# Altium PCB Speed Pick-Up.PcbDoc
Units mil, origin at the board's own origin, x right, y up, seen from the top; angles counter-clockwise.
Board outline 393.7 x 393.7 mil, 2 copper layers (Top Layer, Bottom Layer), stack 61.855 mil thick; 6 components, 4 nets, 13 pads, 4 vias.
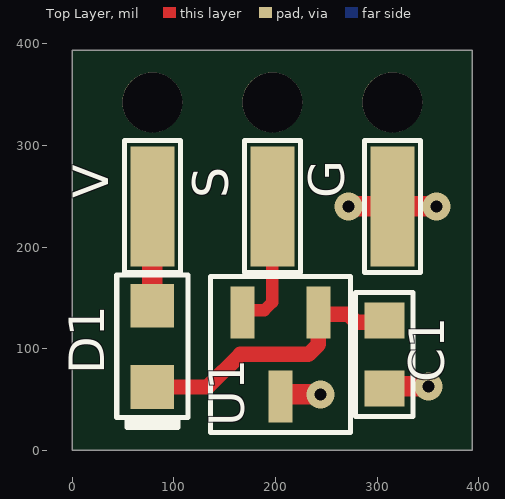
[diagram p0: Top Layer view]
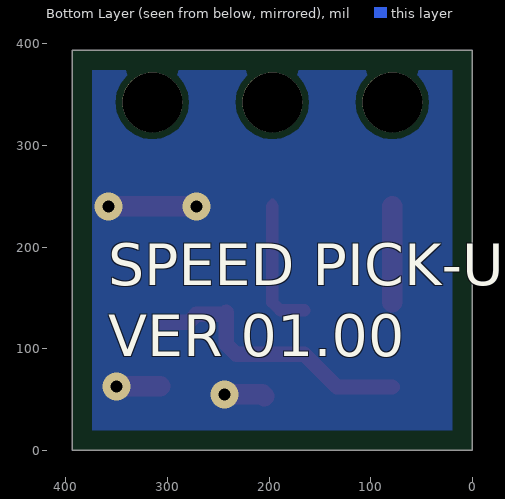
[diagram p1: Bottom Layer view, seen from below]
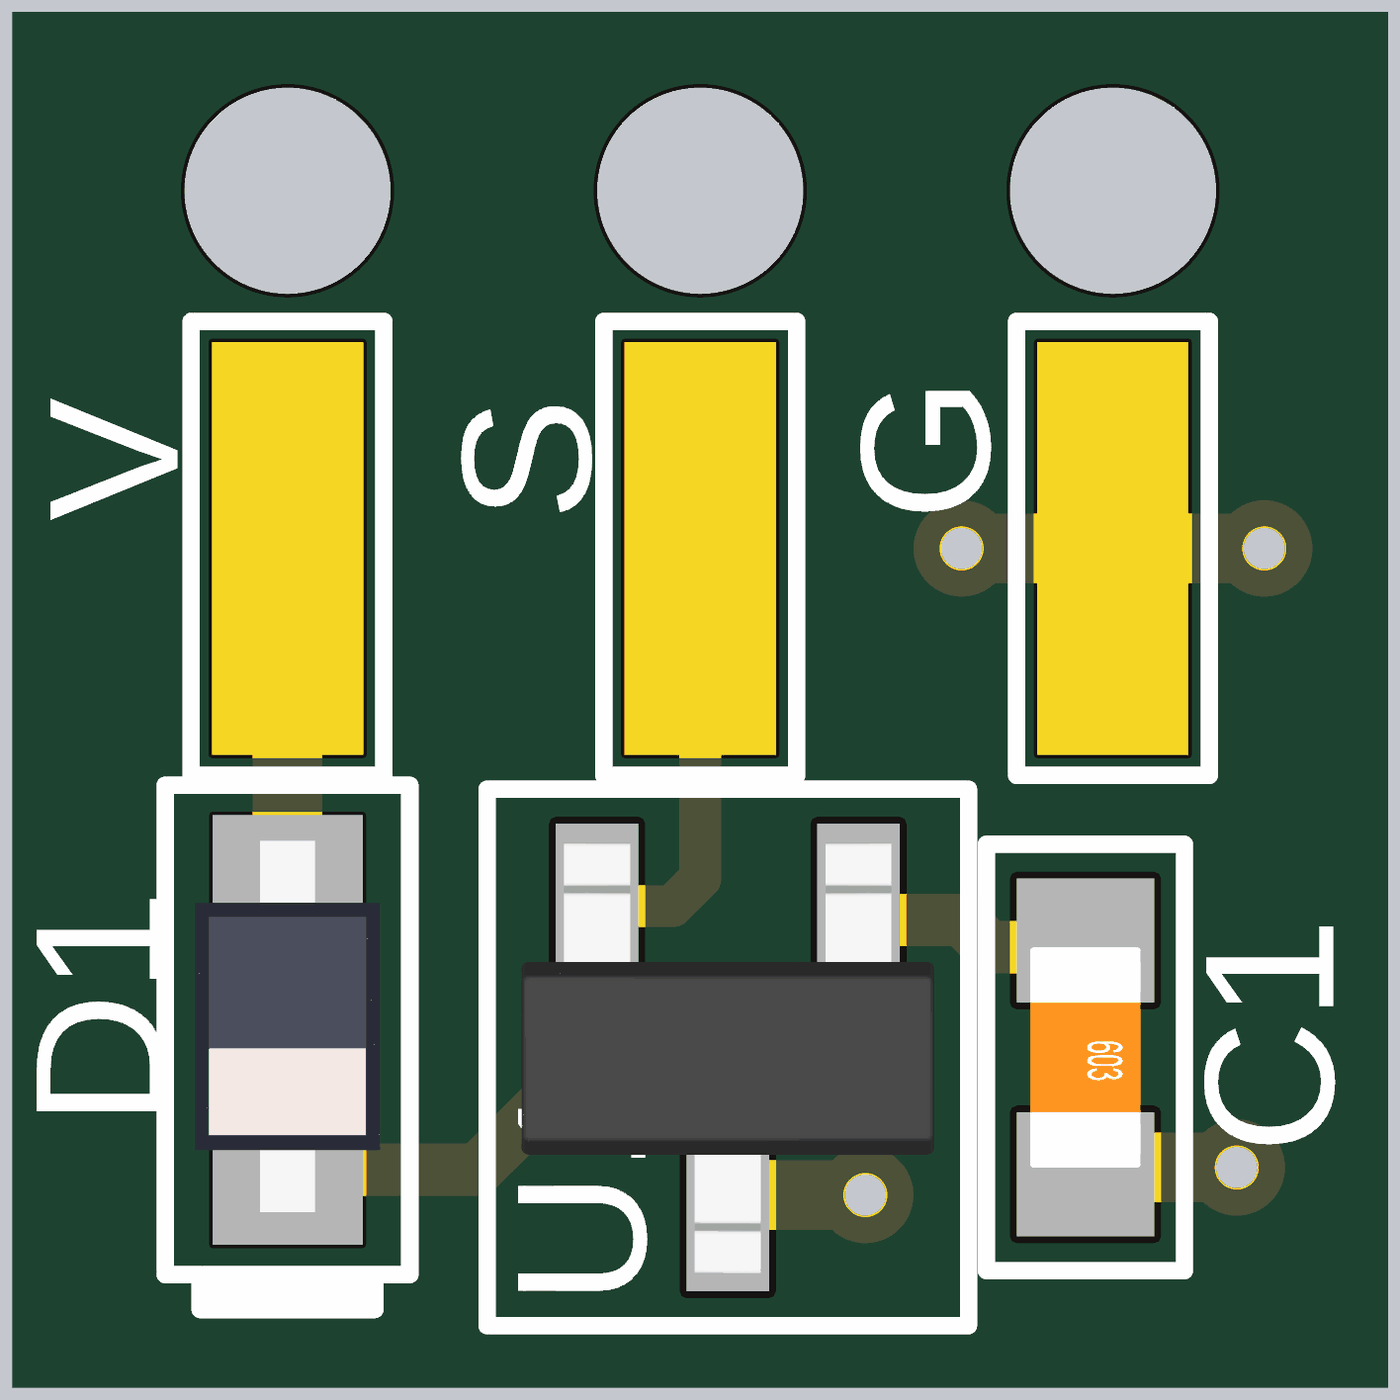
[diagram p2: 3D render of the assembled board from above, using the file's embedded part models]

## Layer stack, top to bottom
Top Solder: solder mask 0.4, Solder Resist, Dk 3.5
Top Layer: signal copper 1.4
Dielectric1: prepreg 59.0551, FR-4, Dk 4.2
Bottom Layer: signal copper 1.4
Bottom Solder: solder mask 0.4, Solder Resist, Dk 3.5

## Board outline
0,0 0,393.7 393.7,393.7 393.7,0

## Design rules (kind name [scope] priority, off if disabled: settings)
Clearance [All] p1: gap=6.69
ComponentClearance [All] p1: gap=0 collisioncheckmode=3 verticalgap=1 showdistances=FALSE
FabricationTestPointUsage TestPointUsage [All] p1: valid=0 allowmultiple=FALSE
FabricationTestpoint Testpoint [All] p1: side=3 testpointundercomponent=TRUE minsize=40 maxsize=100 preferedsize=60 minholesize=0 maxholesize=40 preferedholesize=32 testpointgrid=1 allowsidetop=TRUE allowsidebottom=TRUE usegrid=TRUE gridtolerance=0.01
HoleSize [All] p1: absolutevalues=TRUE maxlimit=196.85 minlimit=9.84 maxpercent=80.000 minpercent=20.000
PlaneClearance [All] p1: clearance=19.68
PolygonConnect PolygonConnect_8 [All vs IsNamedPolygon('Top - GND1-HSK')] p1: connectstyle=Direct reliefconductorwidth=10 reliefentries=4 polygonreliefangle="90 Angle" airgapwidth=10
PolygonConnect PolygonConnect_7 [All vs IsNamedPolygon('Bot - GND1-HSK')] p2: connectstyle=Direct reliefconductorwidth=10 reliefentries=4 polygonreliefangle="90 Angle" airgapwidth=10
PolygonConnect PolygonConnect_6 [All vs IsNamedPolygon('Bot - GND4a') Or  IsNamedPolygon('Bot - GND2a') Or  IsNamedPolygon('Bot - GND3a')] p3: connectstyle=Direct reliefconductorwidth=10 reliefentries=4 polygonreliefangle="90 Angle" airgapwidth=10
PolygonConnect PolygonConnect_5 [All vs IsNamedPolygon('Bot - GND1a')] p4: connectstyle=Direct reliefconductorwidth=10 reliefentries=4 polygonreliefangle="90 Angle" airgapwidth=10
PolygonConnect PolygonConnectVia [All vs isvia] p5: connectstyle=Direct reliefconductorwidth=9.84 reliefentries=4 polygonreliefangle="90 Angle" airgapwidth=10
PolygonConnect PolygonConnect_4 [All vs IsNamedPolygon('Bot - GND2')] p6: connectstyle=Relief reliefconductorwidth=30 reliefentries=4 polygonreliefangle="90 Angle" airgapwidth=10
PolygonConnect PolygonConnect_3 [All vs IsNamedPolygon('Bot - GND1')] p7: connectstyle=Relief reliefconductorwidth=30 reliefentries=4 polygonreliefangle="90 Angle" airgapwidth=10
PolygonConnect PolygonConnect_2 [All vs IsNamedPolygon('Bot - GND4')] p8: connectstyle=Relief reliefconductorwidth=30 reliefentries=4 polygonreliefangle="90 Angle" airgapwidth=10
PolygonConnect PolygonConnect_1 [All vs IsNamedPolygon('Bot - GND3')] p9: connectstyle=Relief reliefconductorwidth=30 reliefentries=4 polygonreliefangle="90 Angle" airgapwidth=10
PolygonConnect [All] p10: connectstyle=Relief reliefconductorwidth=15.75 reliefentries=4 polygonreliefangle="90 Angle" airgapwidth=10
RoutingCorners [All] p1: cornerstyle=45-Degree minsetback=98.43 maxsetback=98.43
RoutingVias [All] p1: holewidth=11.81 width=27.56 viastyle="Through Hole" minholewidth=11.81 minwidth=27.56 maxholewidth=11.81 maxwidth=27.56
ShortCircuit ShortCircuit_LK1 [(InComponent('LK1'))] p1: allowed=TRUE
ShortCircuit ShortCircuit_LK2 [(InComponent('LK2'))] p2: allowed=TRUE
ShortCircuit ShortCircuit_LK3 [(InComponent('LK3'))] p3: allowed=TRUE
ShortCircuit [All] p4: allowed=FALSE
SilkToSolderMaskClearance SilkscreenOverComponentPads [IsPad] p1: minsilkscreentomaskgap=10 clearancetoexposedcopper=TRUE
SolderMaskExpansion [All] p1: expansion=1.97
Width "Width_High Power" [InNetClass('High Power')] p1: maxlimit=59.06 minlimit=19.68 preferedwidth=39.37
Width Width_Power [InNetClass('Power')] p2: maxlimit=39.37 minlimit=11.81 preferedwidth=19.68
Width [All] p3: maxlimit=78.74 minlimit=7.87 preferedwidth=7.87
22 further rules are at their usual default settings.

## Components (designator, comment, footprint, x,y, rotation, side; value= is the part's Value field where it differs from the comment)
C1 "10nF_C0603_50V_10%_X7R" CAPC0603X85N 307.09,94.49 r270 top
D1 "1N4148WS" SOD323 78.74,102.36 r90 top
G "Pad-SMD-1.1x3.0mm-H_Rectangle" "PAD-SMD-1.1x3.0mm Rect" 314.96,240.16 r0 top
S "Pad-SMD-1.1x3.0mm-H_Rectangle" "PAD-SMD-1.1x3.0mm Rect" 196.85,240.16 r0 top
U1 "TLE4946-2K" SOT23 204.72,94.49 r270 top
V "Pad-SMD-1.1x3.0mm-H_Rectangle" "PAD-SMD-1.1x3.0mm Rect" 78.74,240.16 r0 top

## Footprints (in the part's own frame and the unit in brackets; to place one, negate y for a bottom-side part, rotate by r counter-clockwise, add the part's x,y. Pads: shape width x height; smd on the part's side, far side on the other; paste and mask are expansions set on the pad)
CAPC0603X85N [mm] "Chip Capacitor, 0603, 2-Leads, Body 1.6x0.8mm, IPC Medium Density"
  rect 0.9x1 smd paste+0 mask+0.05: 1(-0.85,0) 2(0.85,0)
  silkscreen extent -1.55,-0.72 1.55,0.72, body extent -0.8,-0.4 0.8,0.4, height 0.85
"PAD-SMD-1.1x3.0mm Rect" [mm] "Pad SMD, 1.1x3.0mm Rect"
  rect 1.1x3 smd paste-2.5 mask+0.025: 1(0,0)
  silkscreen extent -0.7,-1.65 0.7,1.65, body extent -0.55,-1.5 0.55,1.5, height 0.01
SOD323 [mil] "Diode, SOD323 2-Leads, Body 1.7x1.25mm, IPC Medium Density"
  rect 43x43 smd mask+0.98: 1(-40,0) 2(40,0)
  silkscreen extent -80,-35 70,35, body extent -52,-27 54,27, height 31
SOT23 [mm] "SOT23, 3-Leads, Body 3.0x1.4mm (max), Pitch 0.95mm, IPC Medium Density"
  rect 1.3x0.6 smd paste+0 mask+0.05: 1(-1.05,0.95) 2(-1.05,-0.95) 3(1.05,0)
  silkscreen extent -1.95,-1.75 1.95,1.75, body extent -1.56,-1.5 1.58,1.5, height 1

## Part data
C1: library part 10nF_0603N_50V_10%_X7R_V, "Cap Ceramic X7R"
D1: library part 1N4148WS_SOD323_H, "Diode Fast Switching Surface Mount"
G S V: "Surface Mount Pad 1.1x3.0mm Rectangle"
U1: library part TLE4946-2K_SOT23, "IC Hall Effect Latch"

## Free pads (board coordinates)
  round 59.06 hole 59.06 unplated mask+1: 0(78.74,342.52) 1(196.85,342.52) 2(314.96,342.52)

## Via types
v1: diameter 27.56, hole 11.81, Top Layer to Bottom Layer, tented both sides, 4 vias

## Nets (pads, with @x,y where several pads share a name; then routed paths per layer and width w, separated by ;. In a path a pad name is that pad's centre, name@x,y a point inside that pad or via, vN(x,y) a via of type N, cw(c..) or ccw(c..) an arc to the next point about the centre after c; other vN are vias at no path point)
GND: C1.2 G.1 U1.3 | length 170.1
  Top Layer w20: U1.3 206.69,55.12 v1(244.09,55.12) ; v1(271.65,240.16) G.1 v1(358.27,240.16) ; C1.2@307.09,62.99 v1(350.39,62.99)
NetD1_2: D1.2 V.1 | length 94.5
  Top Layer w20: D1.2@78.74,145.67 V.1
"SPEED PICK-UP": S.1 U1.2 | length 133.2
  Top Layer w8: S.1 S.1@196.85,244.09
  Top Layer w12: U1.2@165.35,137.8 188.98,137.8 196.85,145.67 S.1
VI: C1.1 D1.1 U1.1 | length 278.5
  Top Layer w15: D1.1 133.23,62.36 165.35,94.49 232.28,94.49 242.13,104.33 U1.1 ; U1.1@244.09,133.86 271.65,133.86 279.53,125.98 C1.1@307.09,125.98

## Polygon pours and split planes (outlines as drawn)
GND on Bottom Layer "Bot - GND" (solid, remove dead copper, pour order 4): 19.68,374.02 374.02,374.02 374.02,19.69 19.68,19.69

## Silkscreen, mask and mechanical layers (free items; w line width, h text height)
Bottom Overlay:
  text "SPEED PICK-UP / VER 01.00" at 358.27,78.74 h70
Board:
  lines w2: 0,0 0,393.7 393.7,393.7 393.7,0 275.59,0 0,0
Mechanical 15:
  lines w2: 78.74,295.28 78.74,413.39 ; 196.85,295.28 196.85,413.39 ; 314.96,295.28 314.96,413.39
